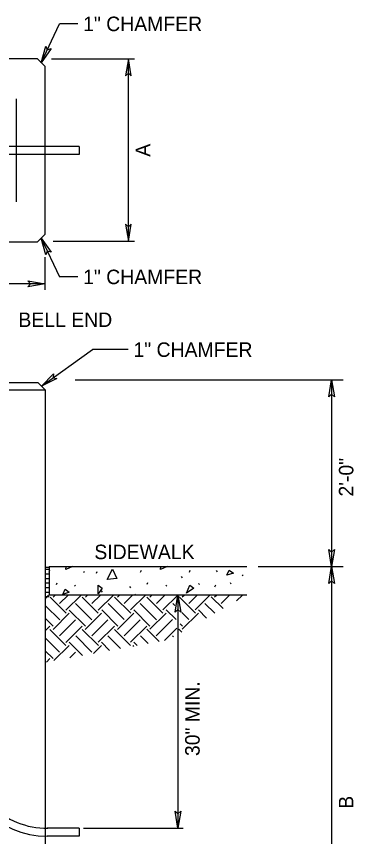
# Model space of a CAD drawing. Extents: x 99836 to 115004, y 99786 to 102182.
# Drawn here: x 107254 to 107533, y 100316 to 100994 of the extents above; entities that cross this region are included whole.
import ezdxf

# ---------------------------------------------------------------- set-up
doc = ezdxf.new("R2010")
doc.units = 0
doc.layers.add('Border Organizer Shape', color=7, linetype='Continuous')

msp = doc.modelspace()

# ---------------------------------------------------------------- linework, layer by layer
at = {"layer": 'Border Organizer Shape'}
for p, q in [((107274.43, 100956.14), (107289.47, 100988.27)), ((107304.66, 100988.26), (107289.47, 100988.27)), ((107271.27, 100959.29), (107126.22, 100959.29)), ((107277.58, 100952.98), (107271.27, 100959.29)), ((107277.58, 100814.24), (107277.58, 100952.98)), ((107282.83, 100959.29), (107351.6, 100959.29)), ((107346.58, 100808.5), (107346.58, 100959.29)), ((107253.93, 100841.04), (107253.93, 100926.18)), ((107277.58, 100886.92), (107209.95, 100886.92)), ((107305.96, 100886.92), (107277.51, 100886.92)), ((107305.96, 100886.92), (107305.96, 100880.3)), ((107277.51, 100880.3), (107209.95, 100880.3)), ((107305.96, 100880.3), (107277.51, 100880.3)), ((107277.58, 100814.24), (107271.27, 100807.93)), ((107274.43, 100811.09), (107289.47, 100778.95)), ((107126.22, 100807.93), (107271.27, 100807.93)), ((107284.36, 100808.5), (107351.6, 100808.5)), ((107277.58, 100768.3), (107277.58, 100795.32)), ((107304.66, 100778.94), (107289.47, 100778.95)), ((107277.58, 100773.24), (107126.22, 100773.24)), ((107274.57, 100688.63), (107316.81, 100718.78)), ((107346.28, 100718.76), (107316.81, 100718.78)), ((107132.25, 100691.64), (107271.56, 100691.64)), ((107271.56, 100691.64), (107277.58, 100685.61)), ((107302.63, 100693.75), (107524.05, 100693.75)), ((107514.59, 100693.75), (107514.59, 100539.45)), ((107126.22, 100685.61), (107277.58, 100685.61)), ((107277.58, 100685.61), (107277.58, 100167.56)), ((107281.05, 100539.45), (107281.04, 100515.8)), ((107281.16, 100539.45), (107444.44, 100539.45)), ((107453.9, 100539.45), (107524.05, 100539.45)), ((107514.59, 100539.45), (107514.59, 100306.62)), ((107280.83, 100538.61), (107277.95, 100538.61)), ((107278.17, 100537.14), (107281.05, 100537.14)), ((107278.17, 100533.36), (107281.05, 100533.36)), ((107280.94, 100534.77), (107281.61, 100536.28)), ((107309.42, 100535.31), (107310.09, 100534.3)), ((107320.05, 100533.83), (107320.73, 100535.34)), ((107356.62, 100534.77), (107357.29, 100536.28)), ((107396.97, 100534.73), (107397.65, 100536.24)), ((107419.21, 100536.11), (107419.88, 100535.1)), ((107440.53, 100532.55), (107441.2, 100531.54)), ((107278.17, 100529.57), (107281.05, 100529.57)), ((107278.17, 100525.79), (107281.05, 100525.79)), ((107287.09, 100524.36), (107287.76, 100525.87)), ((107362.06, 100524.72), (107362.73, 100526.23)), ((107390.25, 100531.05), (107390.92, 100530.03)), ((107404.64, 100525.45), (107405.31, 100524.43)), ((107430.58, 100526.16), (107431.25, 100525.14)), ((107278.17, 100522), (107281.05, 100522)), ((107301.94, 100524.02), (107302.62, 100523.01)), ((107324.07, 100519.23), (107324.74, 100518.22)), ((107347.5, 100522.85), (107348.17, 100521.84)), ((107377.62, 100524.02), (107378.3, 100523.01)), ((107418.04, 100522.67), (107418.71, 100524.19)), ((107278.17, 100518.22), (107281.05, 100518.22)), ((107278.17, 100513.17), (107280.57, 100515.57)), ((107278.17, 100514.44), (107281.05, 100514.44)), ((107444.45, 100515.8), (107281.04, 100515.8)), ((107281.04, 100515.8), (107281.05, 100515.8)), ((107281.72, 100514.05), (107295.1, 100500.67)), ((107284.2, 100514.04), (107285.96, 100515.8)), ((107289.55, 100508.69), (107296.66, 100515.8)), ((107294.91, 100503.34), (107307.36, 100515.8)), ((107308.28, 100514.04), (107321.66, 100500.66)), ((107310.96, 100514.04), (107312.72, 100515.8)), ((107316.31, 100508.69), (107323.42, 100515.8)), ((107321.66, 100503.34), (107334.12, 100515.8)), ((107335.14, 100514.14), (107348.52, 100500.76)), ((107337.62, 100514.13), (107339.29, 100515.8)), ((107342.97, 100508.78), (107349.99, 100515.8)), ((107348.33, 100503.43), (107360.69, 100515.8)), ((107351.56, 100516.59), (107352.23, 100515.58)), ((107361.7, 100514.13), (107375.08, 100500.76)), ((107364.38, 100514.13), (107366.04, 100515.8)), ((107369.73, 100508.78), (107376.74, 100515.8)), ((107375.08, 100503.43), (107387.45, 100515.8)), ((107387.49, 100515.8), (107387.49, 100322.81)), ((107388.56, 100514.23), (107401.94, 100500.86)), ((107391.04, 100514.23), (107392.61, 100515.8)), ((107396.39, 100508.88), (107403.31, 100515.8)), ((107401.75, 100503.53), (107414.02, 100515.8)), ((107415.12, 100514.23), (107424.8, 100504.55)), ((107417.8, 100514.23), (107419.37, 100515.8)), ((107423.15, 100508.88), (107430.07, 100515.8)), ((107435.86, 100510.88), (107440.77, 100515.8)), ((107278.1, 100506.96), (107289.75, 100495.32)), ((107302.93, 100508.69), (107316.31, 100495.31)), ((107329.79, 100508.79), (107343.17, 100495.41)), ((107356.35, 100508.78), (107369.73, 100495.4)), ((107383.21, 100508.88), (107384.88, 100507.21)), ((107409.77, 100508.88), (107417.99, 100500.66)), ((107284.2, 100487.28), (107297.58, 100500.66)), ((107297.58, 100503.34), (107310.96, 100489.96)), ((107310.87, 100487.38), (107324.24, 100500.76)), ((107324.44, 100503.44), (107337.82, 100490.06)), ((107337.62, 100487.38), (107351, 100500.76)), ((107351, 100503.43), (107364.38, 100490.05)), ((107364.29, 100487.47), (107377.66, 100500.85)), ((107377.86, 100503.53), (107385.98, 100495.41)), ((107390.79, 100501.3), (107396.59, 100495.5)), ((107391.04, 100487.47), (107404.42, 100500.85)), ((107404.42, 100503.53), (107411.19, 100496.76)), ((107277.99, 100496.37), (107284.39, 100489.97)), ((107289.55, 100481.93), (107302.93, 100495.31)), ((107316.22, 100482.03), (107329.6, 100495.4)), ((107342.97, 100482.03), (107356.35, 100495.4)), ((107369.64, 100482.12), (107383.02, 100495.5)), ((107389.37, 100492.02), (107391.24, 100490.15)), ((107277.88, 100486.31), (107281.53, 100489.96)), ((107281.53, 100487.28), (107294.91, 100473.91)), ((107294.91, 100476.58), (107308.28, 100489.96)), ((107308.38, 100487.38), (107321.76, 100474.01)), ((107321.57, 100476.67), (107334.95, 100490.05)), ((107334.95, 100487.38), (107348.33, 100474)), ((107348.33, 100476.67), (107361.7, 100490.05)), ((107361.8, 100487.48), (107371.94, 100477.34)), ((107376.36, 100478.14), (107386.62, 100488.4)), ((107388.37, 100487.47), (107390.76, 100485.07)), ((107277.81, 100480.3), (107289.55, 100468.55)), ((107303.03, 100482.03), (107316.41, 100468.65)), ((107329.6, 100482.03), (107340.08, 100471.54)), ((107356.45, 100482.13), (107362.89, 100475.69)), ((107383.02, 100482.12), (107383.96, 100481.18)), ((107284.99, 100461.51), (107297.49, 100474)), ((107297.68, 100476.68), (107308.56, 100465.8)), ((107317.71, 100467.46), (107324.24, 100474)), ((107324.24, 100476.67), (107331.03, 100469.89)), ((107350.19, 100473.38), (107350.91, 100474.09)), ((107351.1, 100476.77), (107353.83, 100474.04)), ((107277.7, 100469.71), (107284.2, 100463.2)), ((107298.08, 100463.89), (107302.84, 100468.65)), ((107278.68, 100460.36), (107281.53, 100463.2)), ((107305.96, 100322.81), (107279.48, 100322.81)), ((107305.96, 100322.81), (107305.96, 100316.19)), ((107309.37, 100322.81), (107391.92, 100322.81)), ((107305.96, 100316.19), (107279.48, 100316.19))]:
    msp.add_line(p, q, dxfattribs=at)
for points in [[(107282.57, 100967.89), (107274.43, 100956.14), (107278.24, 100969.92), (107279.47, 100966.9)], [(107348.97, 100945.19), (107346.58, 100959.29), (107344.18, 100945.19), (107346.58, 100947.4)], [(107344.18, 100822.6), (107346.58, 100808.5), (107348.97, 100822.6), (107346.58, 100820.39)], [(107278.24, 100797.3), (107274.43, 100811.09), (107282.57, 100799.33), (107279.47, 100800.32)], [(107263.48, 100775.63), (107277.58, 100773.24), (107263.48, 100770.85), (107265.7, 100773.24)], [(107287.44, 100694.87), (107274.57, 100688.63), (107284.66, 100698.77), (107284.25, 100695.53)], [(107512.2, 100679.65), (107514.59, 100693.75), (107516.99, 100679.65), (107514.59, 100681.86)], [(107516.99, 100553.55), (107514.59, 100539.45), (107512.2, 100553.55), (107514.59, 100551.33)], [(107512.2, 100525.35), (107514.59, 100539.45), (107516.99, 100525.35), (107514.59, 100527.56)], [(107385.1, 100501.7), (107387.49, 100515.8), (107389.88, 100501.7), (107387.49, 100503.91)], [(107389.88, 100336.92), (107387.49, 100322.81), (107385.1, 100336.92), (107387.49, 100334.7)]]:
    msp.add_lwpolyline(points, close=True, dxfattribs=at)
for points in [[(107294.73, 100536.92), (107295.09, 100539.45)], [(107300.21, 100539.45), (107294.89, 100536.98)], [(107373.06, 100536.91), (107373.42, 100539.45)], [(107378.57, 100539.45), (107373.22, 100536.97)], [(107328.85, 100528.66), (107333.38, 100537.23), (107336.91, 100529.33), (107329.01, 100528.66)], [(107427.97, 100532.1), (107429.98, 100536.3), (107433.34, 100533.78), (107427.97, 100532.1)], [(107292.2, 100516.35), (107294.21, 100520.55), (107297.57, 100518.03), (107292.2, 100516.35)], [(107321.61, 100516.72), (107321.6, 100523.85), (107324.96, 100521.33), (107321.61, 100516.72)], [(107394.56, 100517.35), (107397.28, 100523.85), (107400.64, 100521.33), (107394.56, 100517.35)]]:
    msp.add_lwpolyline(points, dxfattribs=at)
for radius, end in [(72.84, 269.83394), (66.22, 270.4151)]:
    msp.add_arc((107279.48, 100389.03), radius, 180, end, dxfattribs=at)

# ---------------------------------------------------------------- texts
for s, p in [(' 1" CHAMFER', (107304.66, 100982.26)), (' 1" CHAMFER', (107304.66, 100772.94)), (' BELL END', (107251.13, 100737.49)), (' 1" CHAMFER', (107346.28, 100712.76)), ('SIDEWALK', (107318.36, 100545.45))]:
    msp.add_text(s, height=12, dxfattribs=at).set_placement(p)
for s, p in [('A', (107364.58, 100878.37)), ('2\'-0"', (107532.59, 100597.24)), ('30" MIN.', (107405.49, 100382.58)), ('B', (107532.59, 100338.99))]:
    msp.add_text(s, height=12, rotation=90, dxfattribs=at).set_placement(p)

doc.saveas('drawing.dxf')
